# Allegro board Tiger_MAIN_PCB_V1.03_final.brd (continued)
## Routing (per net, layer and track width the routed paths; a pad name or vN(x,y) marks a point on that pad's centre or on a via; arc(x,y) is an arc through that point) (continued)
PMON_PSYS: length 6.6
  BOTTOM w0.203: R238.2 R218.2 231.98,84.12 R232.2 C720.1 232.37,85.95 233.77,85.95 234.94,87.12 U103.1
POWER_TP_ON: length 10.4
  TOP w0.076: 191.47,61.04 191.47,61.24 191.75,61.51 192.07,61.51 192.39,61.19 U1.AM11
  TOP w0.102: 191.47,61.04 191.47,61.04 191.32,60.88 189.93,60.88 189.76,60.7 189.76,59.93 189.4,59.57 188.77,59.57 188.61,59.72 186.1,59.72 184.97,58.59 R382.1
POWSW#: length 36.8
  TOP w0.305: 120.22,8.59 SW1.1 v2(120.22,12.58)
  LAY6 w0.102: v2(120.22,12.58) 121.23,11.58 132.77,11.58 134.59,13.39 v2(147.22,13.39)
  BOTTOM w0.102: D29.N 147.19,13.42 v2(147.22,13.39)
  BOTTOM w0.203: D29.N D17.N 145.2,13.35 R791.1
PROCHOT#_EC: length 6.1
  BOTTOM w0.114: U22.76 44.85,62.26 R426.2 44.23,61.94 42.73,61.94 R407.2 42.23,62.38 41.59,61.74 U23.2
PS_LATCH#: length 10.7
  BOTTOM w0.305: Q57.3 149.19,16.95 Q56.1 148.98,16.95 147.44,18.5 145.61,18.5 145.2,18.09 D17.P 144.49,16.99 143.96,17.52 R792.2
PS_S3CNTRL: length 298.5
  LAY3 w0.102: v2(166.39,35.76) 166.57,35.58 166.57,19.91 173.2,13.28 180.21,13.28 182.66,10.83 192.73,10.83 192.92,10.64 239.82,10.64 243.18,14 243.18,24.84 230.51,37.51 230.51,39.65 235.82,44.95 v2(235.82,46.06)
  LAY6 w0.102: v2(29.41,63.04) 32.24,63.04 42.82,52.46 74.63,52.46 75.53,51.56 89.59,51.56 89.82,51.79 91.92,51.79 93.85,49.86 109.56,49.86 110.37,50.68 111.68,50.68 115.41,46.95 122.79,46.95 124.66,45.08 130.08,45.08 130.83,45.83 135.73,45.83 148.23,33.33 163.96,33.33 v2(166.39,35.76)
  BOTTOM w0.102: v2(29.41,63.04) 29.41,62.15 28.51,61.25 Q45.1 ; Q21.1 v2(235.82,46.06)
  BOTTOM w0.305: Q45.1 27.28,61.25 26.92,61.61 R463.2 R809.2 26.09,64.35 Q46.3
PSMS: length 2
  BOTTOM w0.102: U95.20 73.27,99.52 72.32,100.47 R3009.1
PWM: length 4.9
  TOP w0.305: R3109.2 128.4,90.35 R3110.1 128.39,89.56 R528.1 128.24,88.64 U2529.16 126.28,89.78 R3106.1
PWR_LED: length 112.2
  TOP w0.102: Q49.1 101.93,14.42 v2(101.93,10.33)
  LAY3 w0.102: v2(45.29,64.02) 45.78,63.53 45.78,56.98 47.83,54.92 47.83,36.19 v2(44.43,32.79)
  LAY6 w0.102: v2(101.93,10.33) 101.8,10.2 98.92,10.2 96.35,12.77 92,12.77 89.43,10.2 70.8,10.2 67.13,13.86 57.86,13.86 54.77,16.95 54.77,21.21 53.07,22.92 51.54,22.92 44.43,30.03 v2(44.43,32.79)
  BOTTOM w0.102: v2(45.29,64.02) 45.54,64.02 45.7,63.86 U22.80
PWR_SW: length 20.2
  TOP w0.305: v2(76.25,101.73) 73.75,101.73 71.3,99.28 CN37.4
  BOTTOM w0.305: v2(76.25,101.73) C2781.1 76.25,100.85 75.27,99.87 U95.24
PWRONLATCHG: length 14.4
  TOP w0.305: v2(139.98,23.92) 139.98,16.93 v2(140.89,16.02)
  BOTTOM w0.305: C784.1 R788.1 143.14,15.99 R792.1 C785.2 v2(140.89,16.02) ; Q58.4 v2(139.98,23.92)
R_OUT+: length 1.6
  TOP w0.508: R630.2 7.13,11.5 CN14.2
R_OUT-: length 1.6
  TOP w0.508: CN14.1 R629.2
REXT: length 2
  BOTTOM w0.102: U2526.26 138.55,80.32 137.65,79.41 R2986.2
RLV_AMP: length 2.5
  BOTTOM w0.102: R2987.2 136.88,79.63 137.07,79.82 137.75,79.82 138.15,80.23 U2526.27
RLV_CFG: length 2.4
  BOTTOM w0.203: R2994.2 139.98,79.99 140.15,80.16 U2526.22
  BOTTOM w0.305: R2993.1 R2994.2
RLV_LNK: length 11.7
  TOP w0.152: U2525.7 136.87,73.25 v2(136.86,73.24)
  BOTTOM w0.152: v2(136.86,73.24) 138.31,73.24 140.9,75.83 140.9,76.56 R2996.1 140.44,79.88 140.55,79.99 U2526.21
ROP_SYS_PWROK: length 174.9
  TOP w0.076: 189.04,78.57 189.44,78.18 v2(189.44,78.01) 189.44,77.68 189.11,77.35 189.11,76.74 U1.B6
  TOP w0.109: 189.04,78.57 187.46,80.16 R15.2
  LAY3 w0.087: v2(59.52,57.73) 59.24,58.01 59.24,59.48 59.65,59.89 59.65,69.83 59.81,69.99 59.81,72.25 59.52,72.54 59.52,74.83 59.21,75.14 59.21,75.76 59.39,75.94 59.39,83.78 v2(60.13,84.51)
  LAY6 w0.087: v2(60.13,84.51) 60.14,84.5 84.09,84.5 95.24,73.35 111.09,73.35 111.78,74.04 121.11,74.04 124.34,70.81 138.59,70.81 139.73,71.95 149.85,71.95 152.13,74.23 164.7,74.23 165.47,75 v2(165.89,75)
  BOTTOM w0.102: 185.9,78.35 189.1,78.35 v2(189.44,78.01)
  BOTTOM w0.109: 185.9,78.35 181.82,78.35 180.03,80.15 175.65,80.15 173.88,78.38 168.9,78.38 166.24,75.71 166.24,75.34 v2(165.89,75) ; v2(59.52,57.73) U22.35
ROP_VCCST_PWRGD: length 4.3
  TOP w0.203: v2(47.53,66.66) 47.53,66.09 R830.1 47.21,65.77 R23.2 46.36,65.78 Q74.1
  BOTTOM w0.109: U22.87 47.53,66.66 v2(47.53,66.66)
RSET: length 5.1
  BOTTOM w0.102: U9.46 124.4,37.14 123.61,36.36 122.56,36.36 121.66,35.46 120.96,35.46 R307.2
RSTZ: length 3.3
  BOTTOM w0.254: U95.22 74.27,100.63 C2786.1 R802.2 R3008.2
RTA: length 1
  TOP w0.305: R958.2 120.28,83.06 U2529.8
RTC_RST*: length 30.1
  TOP w0.076: U1.AM16 v2(196.05,60.78)
  LAY3 w0.076: 195.99,57.01 196.42,57.43 196.42,60.41 v2(196.05,60.78)
  LAY3 w0.102: 195.99,57.01 194.65,55.66 193.81,55.66 193.08,54.94 189.98,54.94 186.54,51.49 182.49,51.49 177.77,46.77 v2(177.77,45.13)
  BOTTOM w0.152: R6.1 v2(177.77,45.13) 177.77,44.45 C3.1
RTC_X1: length 24.3
  TOP w0.076: U1.AM18 v2(196.96,60.78)
  LAY3 w0.089: v2(188.02,46.61) 189.11,47.7 190.34,47.7 190.56,47.91 190.56,49.07 192.31,50.82 192.58,50.82 198.24,56.49 198.24,59.69 197.14,60.78 v2(196.96,60.78)
  BOTTOM w0.076: R5.2 187.93,45.99 C6.1 187.93,44.74
  BOTTOM w0.102: R5.2 187.86,46.44 v2(188.02,46.61) ; X2.2 187.93,44.26 187.93,44.74
RTC_X2: length 23.5
  TOP w0.076: U1.AM20 v2(197.87,60.78)
  LAY3 w0.089: v2(197.87,60.78) 197.87,60.37 198.42,59.82 198.42,56.33 192.64,50.55 192.33,50.55 190.81,49.03 190.81,47.8 190.49,47.48 189.5,47.48 v2(188.63,46.61)
  BOTTOM w0.076: 188.75,44.74 C5.1 188.75,46 R5.1
  BOTTOM w0.102: X2.1 188.75,44.11 188.75,44.74 ; R5.1 188.81,46.44 v2(188.63,46.61)
S3_DISCHARGE: length 397.7
  TOP w0.203: v2(154.59,70.67) Q53.1 155.89,72.89 161.28,78.28 162.68,78.28 167.48,83.08 v2(167.48,85.39) ; v2(149.78,39.15) 147.08,41.85 Q67.1 ; Q66.1 178.01,88.05 v2(177.76,87.81)
  TOP w0.254: Q64.1 38.01,67.77 37.21,68.57 Q63.1
  TOP w0.305: v2(38.97,81.11) 38.97,72.72 38.55,72.3 38.07,72.3 Q63.1
  LAY3 w0.203: v2(167.47,36.79) 167.2,36.52 167.2,22.67 168.05,21.81 168.05,19.13 173.63,13.56 180.38,13.56 182.82,11.12 185.88,11.12 187.3,12.54 192.54,12.54 193.87,11.21 239.36,11.21 242.52,14.37 242.52,23.38 229.84,36.06 229.84,44.25 v2(230.7,45.11) ; v2(149.78,39.15) 152.77,42.15 152.77,46.31 148.87,50.21 148.87,57.21 152.39,60.73 152.39,68.47 v2(154.59,70.67)
  LAY3 w0.254: v2(167.48,85.39) 169.3,85.39 172.57,88.67 176.91,88.67 v2(177.76,87.81)
  LAY6 w0.203: v2(167.47,36.79) 166.17,36.79 163.43,34.04 154.88,34.04 v2(149.78,39.15) ; v2(154.59,70.67) 154.27,70.67 152.04,68.44 143.91,68.44 142.21,66.73 122.26,66.73 119.03,69.96 91.93,69.96 88.21,73.68 75.15,73.68 72.28,76.55 48.71,76.55 44.15,81.11 v2(41.36,81.11)
  BOTTOM w0.305: Q52.1 v2(230.7,45.11) ; v2(41.36,81.11) v2(38.97,81.11) 28.28,81.11 27.03,79.87 27.03,75.51 28.51,74.04 Q65.3 29.8,73.56 29.31,73.07 R814.1 R821.2
S4_DISCHARGE: length 5.8
  BOTTOM w0.102: R813.1 237.33,50.07 R812.2 238.65,50.07 239.65,49.07 Q62.3 240.76,49.07 241.14,49.45 Q61.1
SA0_DIM1: length 7.9
  TOP w0.102: CN1.256 173.61,14.89 173.35,15.16 172.4,15.16 170.25,13.01 R491.1 R489.1
SA1_DIM1: length 3.6
  TOP w0.102: R389.1 R436.1 171.98,12.09 172.61,12.72 CN1.260
SA_BOOT: length 1
  BOTTOM w0.305: U54.2 162.15,88.74 R258.1
SA_COPM: length 4.8
  BOTTOM w0.203: C312.1 244.03,91.54 R224.2 242,89.52 U103.24
SA_CSN: length 6.8
  BOTTOM w0.203: C806.2 243.25,84.24 R237.1 242.42,85.07 242.42,87.44 241.95,87.92 U103.28
SA_CSP: length 11.8
  BOTTOM w0.203: U103.27 242.17,88.32 242.8,87.68 242.8,85.21 243.07,84.94 244.77,84.94 244.98,84.74 244.98,84.12 R223.1 ; R223.1 244.73,82.8 R260.1 R221.1 ; R223.1 C311.1
SA_FCCM: length 98.6
  LAY3 w0.635: v1(158.82,88.74) 158.82,91.5 161.45,94.13 189.17,94.13 191.3,96.26 206.71,96.26 207.02,95.94 210.05,95.94 210.84,96.73 228.9,96.73 229.21,97.05 237.62,97.05 242.82,91.85 242.82,89.1 241.64,87.93 v1(241.64,87.18)
  BOTTOM w0.203: 241.5,87.32 241.3,87.52 U103.29
  BOTTOM w0.305: U54.7 v1(158.82,88.74)
  BOTTOM w0.635: 241.5,87.32 v1(241.64,87.18)
SA_HG_DRV: length 4
  TOP w0.635: v1(161.63,92.39) 161.61,92.37 R183.2
  BOTTOM w0.305: U54.1 161.45,89.69
  BOTTOM w0.635: v1(161.63,92.39) 161.45,92.22 161.45,89.69
SA_LG_DRV: length 4.8
  TOP w0.635: Q73.3 v1(162.42,87.07)
  BOTTOM w0.305: U54.5 159.55,87.36 159.85,87.07
  BOTTOM w0.635: 159.85,87.07 v1(162.42,87.07)
SA_PHASE: length 98.6
  LAY3 w0.254: v2(246.64,85.96) 246.11,86.5 244.35,86.5 243.58,85.72 240.01,85.72 238.95,86.78 237.93,86.78 236.28,88.44 236.28,89.11 233.99,91.4 233.54,91.4 232.31,92.62 210.96,92.62 210.41,93.17 206.24,93.17 205.84,92.78 204.67,92.78 203.99,93.46 201.47,93.46 200.79,92.78 192.41,92.78 191.29,91.66 168.01,91.66 v2(167.11,90.76)
  BOTTOM w0.203: v2(246.64,85.96) 247.15,85.45 247.15,83.08 246.4,82.33 245.8,82.33 R260.2
  BOTTOM w0.305: U54.8 159.55,89.55
  BOTTOM w0.508: C740.1 163.36,92.49 v1(163.35,92.49) 162.35,93.49 160.74,93.49 159.55,92.31 159.55,89.55
SA_PWM: length 91.3
  LAY3 w0.635: v1(163.48,87.1) 163.48,88.7 167.52,92.73 189.87,92.73 192.08,94.94 206.02,94.94 206.43,94.53 214.93,94.53 215.98,95.58 232.76,95.58 233.99,94.34 236.8,94.34 240.37,90.78 240.37,86.83 v1(240.72,86.48)
  BOTTOM w0.203: U103.30 240.52,86.66
  BOTTOM w0.305: U54.3 162.35,88.24 163.48,87.11 v1(163.48,87.1)
  BOTTOM w0.635: 240.52,86.66 240.7,86.48 v1(240.72,86.48)
SD_CDZ: length 20.2
  TOP w0.102: v2(73.76,99.95) 72.6,98.79 72.6,92.86 74.95,90.51 80.37,90.51 81.68,89.2 CN37.11
  BOTTOM w0.102: v2(73.76,99.95) 73.77,99.95 U95.21
SD_CLK: length 10.3
  TOP w0.102: v2(72.2,90.75) 73.8,89.15 CN37.5
  BOTTOM w0.102: v2(72.2,90.75) 71.14,91.81 71.14,96.2 71.35,96.41 U95.14
SD_CMD: length 12.3
  TOP w0.102: v2(67.23,93.79) 66.3,92.86 CN37.2
  BOTTOM w0.102: v2(67.23,93.79) 70.36,96.91 U95.15
SD_D0: length 13.2
  TOP w0.102: CN37.7 78.8,89.31 78.44,89.66 74.29,89.66 v2(73.12,90.83)
  BOTTOM w0.102: U95.13 72.02,91.93 v2(73.12,90.83)
SD_D1: length 13.2
  TOP w0.102: v2(74.02,90.77) 74.81,89.97 79.65,89.97 80.43,89.19 CN37.8
  BOTTOM w0.102: U95.12 72.77,92.02 v2(74.02,90.77)
SD_D2: length 15.5
  TOP w0.102: v2(65.94,93.77) 65.94,93.72 64.29,92.06 64.29,92.05 61.3,89.06 CN37.9
  BOTTOM w0.102: U95.17 70.09,97.91 v2(65.94,93.77)
SD_D3: length 13.9
  TOP w0.102: v2(66.58,93.79) 63.8,91.01 CN37.1
  BOTTOM w0.102: v2(66.58,93.79) 70.21,97.41 U95.16
SD_RCOMP: length 12.5
  TOP w0.254: v2(189.72,65.81) 189.72,66.08 U1.AB7
  TOP w0.305: v2(179.16,66.25) 179.33,66.08 R74.2
  LAY6 w0.254: v2(189.72,65.81) 189.72,65.65 189.32,65.26 186.37,65.26 185.87,65.76 179.65,65.76 v2(179.16,66.25)
SD_WP: length 14.4
  TOP w0.102: CN37.10 82.97,89.18 82.72,89.43 82.02,89.43 80.61,90.84 75.4,90.84 v2(74.58,91.66)
  BOTTOM w0.102: U95.10 73.77,92.47 v2(74.58,91.66)
SKL_CNL*: length 12.6
  TOP w0.076: R716.1 231.03,81.38 230.41,80.76 224.42,80.76 223.72,80.06 223.72,79.32 222.92,78.52 222.92,76.57 U1.C64
SLPS3#_CONTROL: length 28.2
  TOP w0.305: R807.2 v2(28.56,79.83)
  TOP w0.406: R810.2 29.95,61.58 v2(29.98,61.6)
  BOTTOM w0.305: R806.2 25.16,60.3 Q45.3 26.73,60.55 29.49,60.55 29.98,61.03 v2(29.98,61.6) 30.33,61.96 30.33,67 32.03,68.7 32.03,76.46 30.47,78.02 29.19,78.02 28.56,78.65 v2(28.56,79.83)
SM_INTRUDER*: length 27.2
  TOP w0.076: U1.AP16 v2(196.05,59.51)
  LAY3 w0.076: v2(196.05,59.51) 195.69,59.15 195.69,57.04
  LAY3 w0.102: 195.69,57.04 194.62,55.98 193.74,55.98 192.89,55.13 189.24,55.13 185.96,51.85 180,51.85 178.2,50.05 v2(175.49,50.05)
  BOTTOM w0.102: v2(175.49,50.05) 175.44,49.99 R12.1
SM_RCOMP_0: length 20
  TOP w0.254: U1.AR18 v2(196.96,58.88)
  TOP w0.305: R53.2 v2(182.94,49.12)
  LAY6 w0.152: 196.47,57.3 196.47,58.39 v2(196.96,58.88)
  LAY6 w0.254: 188.88,51.93 191.32,51.93 194.59,55.2 194.59,55.42 196.47,57.3
  LAY6 w0.305: 188.88,51.93 185.75,51.93 v2(182.94,49.12)
SM_RCOMP_1: length 16.6
  TOP w0.254: U1.AT18 v2(196.96,58.24)
  TOP w0.305: v2(189.51,48.1) 189.32,47.91 R52.2
  LAY3 w0.305: v2(189.51,48.1) 189.51,50.91 190.19,51.58 192.83,51.58 197.48,56.23 197.48,57.88 197.12,58.24 v2(196.96,58.24)
SM_RCOMP_2: length 18.2
  TOP w0.254: U1.AU18 v2(196.96,57.61)
  TOP w0.305: R51.2 v2(183.72,49.12)
  LAY3 w0.152: v2(196.96,57.61) 196.96,57.17 196.77,56.99
  LAY3 w0.254: 184,49.41 185.21,50.62 188.38,50.62 191.15,53.39 192.73,53.39 194.29,54.95 194.73,54.95 196.77,56.99
  LAY3 w0.305: 184,49.41 184,49.4 v2(183.72,49.12)
SM_VREF_DQ1: length 88.7
  TOP w0.203: R512.2 v2(229.63,48.62)
  LAY3 w0.203: v2(229.63,48.62) 229.63,45.77 229.11,45.25 229.11,35.75 241.85,23.01 241.85,14.56 239.99,12.7 195.72,12.7 v2(195.03,12.01)
  BOTTOM w0.203: R476.1 v2(195.03,12.01)
SMB_CLK: length 17.8
  TOP w0.076: U1.R7 v2(189.63,69.01)
  TOP w0.109: Q2.3 175.88,72.97 176.12,72.73 177.96,72.73 178.63,72.06 178.63,71.27 R82.2 179.18,70.12 v2(179.11,70.04)
  LAY6 w0.076: v2(189.63,69.01) 189.27,69.38 188.27,69.38 188,69.64
  LAY6 w0.102: 188,69.64 179.51,69.64 v2(179.11,70.04)
SMB_CLK_BT: length 2.2
  BOTTOM w0.109: U22.110 53.12,72.55 52.78,72.89 52.78,72.89 R388.2
SMB_CLK_S2: length 103
  TOP w0.109: v2(136.05,28.85) 149.15,28.85 150.51,27.49 162.3,27.49 166.18,23.6 166.18,21.32 166.71,20.8 168.72,20.8 v2(169,21.08) 170.67,19.41 173.87,19.41 174.36,19.91 CN1.253 ; v2(171.21,70.25) 171.49,70.52 R85.1 171.51,72.02 Q2.2
  LAY3 w0.087: v2(171.21,70.25) 171.16,70.3 171.01,70.3 169.25,68.54 169.25,65.49 168.67,64.91 168.67,62.44 167.41,61.17 167.41,58.78 168.74,57.45 168.74,56.23 169.31,55.66 169.31,53.48 169.98,52.8 169.98,52.41 169.64,52.07 169.64,48.05 169.95,47.74 169.95,39.48 169.38,38.91 169.38,24.55 169.66,24.27 169.66,21.74 v2(169,21.08)
  BOTTOM w0.109: R3001.2 135.95,28.95 v2(136.05,28.85)
SMB_DATA: length 21.1
  TOP w0.076: U1.R8 v2(190.27,69.01)
  TOP w0.109: Q3.3 175.29,69.63 175.79,70.13 175.79,71.65 176.31,72.17 177.89,72.17 178.22,71.84 178.22,70.27 v2(178.45,70.04) 178.64,69.86 R83.2
  LAY6 w0.076: v2(190.27,69.01) 189.74,69.55 188.48,69.55 188.35,69.67
  LAY6 w0.102: 188.35,69.67 188.12,69.91 182.12,69.91 181.56,70.47 178.88,70.47 v2(178.45,70.04)
SMB_DATA_BT: length 2
  BOTTOM w0.109: R393.2 53.52,73.72 U22.111
SMB_DATA_S2: length 104.6
  TOP w0.109: v2(170.98,68.65) 171,68.67 R84.1 171.62,68.68 Q3.2 ; v2(136.11,28.28) 149.03,28.28 150.36,26.95 162.15,26.95 165.69,23.4 165.69,21.1 166.5,20.29 v2(169.09,20.29) 170.46,18.92 173.67,18.92 174.11,18.47 CN1.254
  LAY3 w0.087: v2(169.09,20.29) 170.2,21.4 170.2,24.48 169.88,24.8 169.88,38.71 170.44,39.27 170.44,47.9 170.11,48.24 170.11,51.82 170.46,52.18 170.46,53.02 169.78,53.7 169.78,55.96 169.23,56.51 169.23,57.79 167.87,59.15 167.87,60.96 169.16,62.24 169.16,64.66 169.74,65.25 169.74,68.32 170.85,69.43 171.07,69.43 171.32,69.18 171.32,69 v2(170.98,68.65)
  BOTTOM w0.109: R3000.2 135.98,28.15 v2(136.11,28.28)
SMB_L1CLK_PCH: length 143.5
  TOP w0.076: R57.2 179.02,68.26 v2(179.08,68.33) ; U1.W3 187.48,67.45 187.29,67.57 187.1,67.57 186.86,67.52 186.6,67.57 185.09,67.57 185.01,67.49 182.92,67.49
  TOP w0.102: R57.2 179.52,67.19 182.35,67.19 182.65,67.49 182.92,67.49
  LAY6 w0.076: 176.55,67.64 177.61,68.7 178.71,68.7 v2(179.08,68.33)
  LAY6 w0.102: 176.55,67.64 174.54,67.64 173.94,68.23 164.55,68.23 163.56,69.22 155.8,69.22 153.31,66.73 144.81,66.73 141.76,63.69 122.37,63.69 117.38,68.68 91.59,68.68 87.71,72.55 73.31,72.55 71.56,74.3 55.31,74.3 v2(54.36,75.25)
  BOTTOM w0.114: R396.1 v2(54.36,75.25)
SMB_L1DATA_PCH: length 140.3
  TOP w0.076: v2(181.73,68.32) 181.78,68.26 R58.2 181.82,67.75 186.56,67.75 186.82,67.69 186.9,67.69 187.08,67.73 187.34,67.73 187.42,67.68 187.71,67.68 U1.V3
  LAY6 w0.076: v2(181.73,68.32) 181.34,67.93 180.17,67.93 179.19,68.91 176.62,68.91 176.45,68.73 176.13,68.73
  LAY6 w0.102: 176.13,68.73 172.2,68.73 171.42,69.52 155.69,69.52 153.12,66.94 144.72,66.94 141.93,64.14 122.62,64.14 117.82,68.94 91.88,68.94 87.88,72.94 73.7,72.94 72.07,74.58 57.76,74.58 v2(57.04,75.3)
  BOTTOM w0.114: R397.1 v2(57.04,75.3)
SMBCLK: length 5.3
  BOTTOM w0.109: R326.2 121.22,46.26 121.53,45.94 123.4,45.94 124,45.34 U9.14
SMBDATA: length 5
  BOTTOM w0.109: U9.15 124.4,45.65 R323.1 R321.1 122,46.47 R325.2
SMC_EXTSMI#: length 136.5
  TOP w0.076: U1.L6 v2(188.98,71.02) ; R61.2 179.78,72.2 v2(180.16,71.82)
  LAY3 w0.102: v2(188.98,71.02) 188.86,70.9 181.16,70.9 180.24,71.82 v2(180.16,71.82) ; v2(71.34,61.98) 73,63.65 73,72.2 v2(74.45,73.64)
  LAY6 w0.076: v2(180.16,71.82) 179.77,71.43 177.89,71.43 177.58,71.12 176.37,71.12
  LAY6 w0.102: v2(74.45,73.64) 74.67,73.43 88.03,73.43 91.88,69.58 118.6,69.58 121.72,66.45 142.33,66.45 144.04,68.16 152.62,68.16 155.28,70.81 165.85,70.81 166.72,71.67 171.87,71.67 173.61,69.93 174.85,69.93 176.03,71.12 176.37,71.12
  BOTTOM w0.102: R403.1 v2(71.34,61.98)
SMC_ONOFF#: length 131.4
  LAY3 w0.102: v2(59.21,50.59) 59.2,50.61 59.2,56.69 58.79,57.09 58.79,59.53 59.38,60.12 59.38,70.44 v2(59.33,70.49)
  LAY6 w0.102: v2(147.19,17.95) 136.95,28.19 136.95,35.09 134.8,37.24 133.68,37.24 127.56,43.35 119.87,43.35 119.44,43.79 116.44,43.79 113.96,46.26 110.57,46.26 108.53,48.31 96.98,48.31 93.58,44.9 87.28,44.9 86.26,45.92 67.05,45.92 61.88,51.09 59.71,51.09 v2(59.21,50.59)
  BOTTOM w0.102: v2(59.33,70.49) 59.12,70.7 U22.125
  BOTTOM w0.203: v2(147.19,17.95) 147.19,17.95 D29.P
SMC_RUNTIME_SCI#: length 151
  TOP w0.076: v2(190.9,70.08) 191.16,70.47 U1.N9 ; R62.2 180.56,72.07 v2(180.81,71.82)
  LAY3 w0.102: v2(65.31,75.59) 65.33,75.56 v2(65.33,61.26) ; v2(180.81,71.82) 180.89,71.82 181.38,71.33 188.42,71.33 188.56,71.47 189.21,71.47 190.12,70.56 190.43,70.56 v2(190.9,70.08)
  LAY6 w0.076: v2(180.81,71.82) 180.81,71.63 180.42,71.24 178.08,71.24 177.56,70.72
  LAY6 w0.102: 177.56,70.72 176.09,70.72 175.07,69.71 173.49,69.71 171.8,71.4 166.93,71.4 166.06,70.52 155.28,70.52 152.67,67.92 144.12,67.92 142.44,66.23 121.29,66.23 118.31,69.21 91.95,69.21 87.97,73.2 74.3,73.2 71.91,75.59 v2(65.31,75.59)
  BOTTOM w0.102: R410.1 65.33,61.25 v2(65.33,61.26)
SMC_SHUTDOWN#: length 147.8
  LAY3 w0.102: v2(43.35,64.87) 43.99,64.24 43.99,55.98 44.93,55.04 44.93,53.79 v2(47.25,51.47)
  LAY6 w0.102: v2(155.07,17.72) 150.32,22.47 150.32,26.02 134.33,42.01 131.16,42.01 129.46,43.71 120.43,43.71 119.22,44.92 115.73,44.92 114.04,46.6 110.81,46.6 108.84,48.57 96.88,48.57 93.52,45.21 87.6,45.21 86.58,46.22 67.25,46.22 62.01,51.47 v2(47.25,51.47)
  BOTTOM w0.102: v2(43.35,64.87) 44.04,64.87 R395.2
  BOTTOM w0.305: Q57.1 151.2,15.42 R789.2 153.66,15.42 155.07,16.82 v2(155.07,17.72)
SMC_WAKE_SCI#: length 142.1
  TOP w0.076: U1.AM15 v2(195.13,60.78)
  LAY3 w0.076: v2(195.13,60.78) 194.67,60.32 194.67,59.81 194.21,59.36 194.04,59.36 193.67,58.99 193.67,57.97 192.19,56.49 190.59,56.49 190.11,56.97 188.37,56.97 187.62,56.22 182.82,56.22 179.74,53.13 176.13,53.13
  LAY3 w0.102: 176.13,53.13 175.62,53.13 173.3,50.81 v2(173.3,49.21)
  LAY6 w0.102: v2(72.17,57.46) 72.79,58.09 91.95,58.09 92.86,57.18 97.66,57.18 98.51,56.33 113.51,56.33 118.46,51.38 143.06,51.38 146.32,48.12 155.26,48.12 156.65,49.5 163.37,49.5 164.12,48.74 167.91,48.74 168.95,49.79 172.71,49.79 v2(173.3,49.21)
  BOTTOM w0.102: R412.1 71.47,61.14 72.2,60.41 72.2,57.5 v2(72.17,57.46) ; R19.2 172.88,49.63 v2(173.3,49.21)
SOC_CATERR*: length 11.9
  TOP w0.076: R29.2 227.2,83.51 226.57,82.87 TP18.1 226.3,82.25 224.35,82.25 222.83,80.73 222.83,79.66 221.99,78.82 221.99,77.83 221.83,77.68 221.83,77.32 221.87,77.22 221.87,77.03 221.83,76.94 221.83,76.69 221.97,76.21 221.97,76.09 222.05,75.83 222.05,75.83 U1.D63
SOC_THRMTRIP*: length 12
  TOP w0.076: U1.C63 222.08,76.46 222,76.71 222,76.89 222.06,77.08 222.06,77.23 222,77.34 222,77.6 222.22,77.82 222.22,78.82 223.01,79.6 223.01,80.68 224.41,82.08 227.09,82.08 227.47,82.46 TP20.1 227.97,83.48 R28.2
SPK_L+: length 269.7
  TOP w0.508: v1(245.86,18.65) 245.84,18.67 R628.1
  LAY6 w0.508: v1(13.58,24.27) 13.58,25.52 22.15,34.1 38.02,34.1 46.06,26.05 46.06,14.23 47.7,12.59 57.45,12.59 60.8,9.24 89.83,9.24 92.09,11.5 95.52,11.5 97.75,9.27 117.21,9.27 118.51,10.57 125.92,10.57 127.16,9.33 145.1,9.33 147.41,11.64 150.75,11.64 153.13,9.26 237.53,9.26 243.53,15.26 243.53,18.86 244.23,19.55 244.95,19.55 v1(245.86,18.65)
  BOTTOM w0.203: 13.84,23.37 14.33,22.87 U16.42
  BOTTOM w0.406: v1(13.58,24.27) 13.84,24.02 13.84,23.37
SPK_L-: length 266.5
  TOP w0.508: v1(244.64,18.77) 244.57,18.83 R627.1
  LAY6 w0.508: v1(14.45,24.39) 14.45,25.47 22.4,33.42 37.65,33.42 45.43,25.64 45.43,13.89 47.39,11.92 57,11.92 60.31,8.61 90.12,8.61 92.37,10.85 95.25,10.85 97.46,8.63 117.68,8.63 119,9.95 125.64,9.95 126.9,8.7 145.43,8.7 147.75,11.01 150.44,11.01 152.82,8.63 237.97,8.63 244.64,15.3 v1(244.64,18.77)
  BOTTOM w0.203: U16.43 14.73,22.76
  BOTTOM w0.305: 14.73,22.76 14.73,23.19
  BOTTOM w0.406: v1(14.45,24.39) 14.53,24.3 14.53,23.38 14.73,23.19
SPK_R+: length 19.3
  TOP w0.508: v2(15.99,23.05) 15.99,22.92 17.54,21.37 17.54,16.92 12.15,11.53 R630.1
  BOTTOM w0.203: v2(15.99,23.05) 15.53,22.59 U16.45
SPK_R-: length 18.1
  TOP w0.508: R629.1 12.46,12.75 16.87,17.16 16.87,21.1 15.39,22.58 v2(15.39,23.18)
  BOTTOM w0.203: v2(15.39,23.18) 15.13,22.93 U16.44
SRTCRST*: length 28.9
  TOP w0.076: v2(196.96,60.15) 196.57,60.54 U1.AN18
  LAY3 w0.076: 194.77,55.41 196.6,57.24 196.6,59.79 v2(196.96,60.15)
  LAY3 w0.102: v2(179.18,45.13) 179.18,47.78 182.59,51.19 186.71,51.19 190.26,54.75 193.24,54.75 193.9,55.41 194.77,55.41
  BOTTOM w0.152: R7.1 v2(179.18,45.13) 179.18,44.44 C4.1
SSD_CK_REQ_N: length 17.9
  TOP w0.102: R181.1 82.85,50.62 81.84,49.61 81.84,41.84 80.42,40.42 CN5.52
SSD_CLK_REQ*: length 123.5
  TOP w0.076: R253.2 183.73,52.69 184.76,53.73 186.82,53.73 187.47,54.38 187.8,54.38 187.99,54.57 187.99,55.11 188.14,55.27 188.14,55.65 188.27,55.77 188.27,56.37 188.61,56.71 188.98,56.71 189.4,57.13 189.4,57.53 189.69,57.82 189.69,58.18 U1.AT7
  TOP w0.102: v2(81.87,57.3) 81.9,57.26 R181.2 81.9,56.19 R180.2 ; v2(180.52,50.19) 181.11,49.6 183.1,49.6 183.32,49.82 183.32,51.15 R253.2
  LAY6 w0.102: v2(180.52,50.19) 180.43,50.19 179.48,49.23 173.94,49.23 173.41,48.7 171.11,48.7 170.52,49.3 168.95,49.3 168.05,48.4 165.04,48.4 164.55,47.9 163.52,47.9 162.5,48.92 156.86,48.92 155.55,47.61 145.97,47.61 142.64,50.94 118.17,50.94 113.32,55.78 97.81,55.78 96.87,56.73 92.56,56.73 91.81,57.48 82.05,57.48 v2(81.87,57.3)
SSD_PCIE_CLK_DN: length 180.9
  TOP w0.076: U1.B42 211,77.01 211.32,77.33 211.32,81 211.05,81.27 v2(210.35,81.27)
  TOP w0.109: R187.1 90.29,39.76 90.73,39.76 91.22,39.76 v2(91.42,39.96)
  LAY3 w0.087: v2(98.97,77.75) 99.8,77.75 100.49,77.06 100.49,73.16 87.06,59.73 87.06,55.3 83.55,51.79 83.55,43.67 87.47,39.75 91.2,39.75 v2(91.42,39.96)
  LAY6 w0.076: 189.9,81.01 189.92,81.01 190.79,81.89 197.21,81.89 198.86,83.54 199.81,83.54 201.59,85.31 202.77,85.31 205.8,82.29 207.68,82.29 208.7,81.27 v2(210.35,81.27)
  LAY6 w0.087: v2(98.97,77.75) 102.47,77.75 104.41,79.69 114.61,79.69 117.56,76.73 123.81,76.73 125.54,78.47 130.35,78.47 130.66,78.16 135.79,78.16 137.36,76.59 139.74,76.59 140.85,77.69 148.41,77.69 149.95,79.23 155.2,79.23 157.73,81.76 171.94,81.76 172.78,80.93 173.74,80.93 174.69,81.87 177.13,81.87 177.68,82.42 185.13,82.42 186.54,81.01 189.9,81.01
SSD_PCIE_CLK_DP: length 181
  TOP w0.076: U1.A42 211.16,77.61 211.16,80.93 210.98,81.11 210.77,81.11 210.67,81.01 210.67,80.75 210.59,80.67 v2(210.35,80.67)
  TOP w0.109: R194.1 90.27,39.54 90.73,39.54 91.24,39.54 v2(91.42,39.36)
  LAY3 w0.087: v2(98.97,77.15) 99.39,77.57 99.72,77.57 100.3,76.98 100.3,73.23 86.88,59.81 86.88,55.38 83.36,51.86 83.36,43.6 87.39,39.56 91.21,39.56 v2(91.42,39.36)
  LAY6 w0.076: 189.9,80.83 189.97,80.83 190.86,81.72 197.28,81.72 198.93,83.37 199.88,83.37 201.66,85.15 202.7,85.15 205.73,82.13 207.61,82.13 208.63,81.11 209.98,81.11 210.05,81.03 210.05,80.78 210.16,80.67 v2(210.35,80.67)
  LAY6 w0.087: 189.9,80.83 186.46,80.83 185.05,82.24 177.76,82.24 177.21,81.69 174.76,81.69 173.82,80.74 172.7,80.74 171.86,81.58 157.81,81.58 155.28,79.05 150.03,79.05 148.49,77.51 140.92,77.51 139.82,76.41 137.28,76.41 135.71,77.97 130.59,77.97 130.27,78.29 125.62,78.29 123.88,76.55 117.49,76.55 114.53,79.51 104.48,79.51 102.55,77.57 99.32,77.57 99.18,77.43 99.18,77.36 v2(98.97,77.15)
SSD_PEDET: length 126.6
  TOP w0.076: U1.G4 188.48,73.9 188.22,73.64 186.24,73.64 v2(185.54,72.94)
  TOP w0.102: R174.2 90.78,35.13 98.61,42.96 102.72,42.96 104.92,45.16 104.92,58.57 v2(107.49,61.13)
  LAY6 w0.076: 177.02,71.76 177.35,72.09 178.88,72.09 179.24,72.45 183.29,72.45 184.14,73.3 185.16,73.3 185.51,72.94 v2(185.54,72.94)
  LAY6 w0.102: 177.02,71.76 172.94,71.76 172.28,72.42 153,72.42 150.67,70.09 141.51,70.09 140.3,68.88 122.66,68.88 120.01,71.53 115.93,71.53 v2(115.85,71.46)
  BOTTOM w0.102: v2(107.49,61.13) 115.85,69.5 v2(115.85,71.46)
SSD_SATA_DEVSLP: length 136.6
  TOP w0.076: v2(179.53,71.81) 179.91,71.43 181.83,71.43 182.95,72.55 186.46,72.55 U1.J1
  TOP w0.102: R175.1 v2(76.77,57.11)
  LAY3 w0.102: v2(76.81,76.37) 76.77,76.33 v2(76.77,57.11)
  LAY6 w0.076: v2(179.53,71.81) 179.53,71.78 179.42,71.66 177.79,71.66 177.48,71.34 176.6,71.34
  LAY6 w0.102: 176.6,71.34 172.64,71.34 171.96,72.02 153.8,72.02 151.34,69.55 142.65,69.55 140.85,67.75 123.16,67.75 119.88,71.03 94.15,71.03 88.27,76.91 77.35,76.91 v2(76.81,76.37)
SSD_SATA_RXN1: length 104.2
  TOP w0.076: v2(197.92,73.74) 198.02,73.74 U1.G21
  TOP w0.109: C2840.1 106.5,72.47 106.78,72.19 110.05,72.19 112.58,74.72 112.58,76.49 v2(112.39,76.68)
  LAY6 w0.076: 188.39,77.48 188.4,77.47 188.4,77.47 188.44,77.43 188.58,77.43 188.59,77.44 196.37,77.44 197.33,76.49 197.33,74.15 197.49,73.99 197.78,73.99 197.92,73.85 v2(197.92,73.74)
  LAY6 w0.087: v2(112.39,76.68) 112.59,76.48 112.59,76.13 113.44,75.28 123.49,75.28 124.09,74.67 134.16,74.67 134.47,74.36 145.24,74.36 145.88,75 149.45,75 151.16,76.72 159.07,76.72 160.93,78.57 164.41,78.57 165.31,79.47 166.81,79.47 167.65,78.63 171.91,78.63 172.59,77.96 175.08,77.96 176.78,79.65 180.28,79.65 181.4,78.53 187.33,78.53 188.16,77.7 188.17,77.7 188.39,77.48
SSD_SATA_RXP1: length 104.2
  TOP w0.076: U1.F21 198.02,74.39 v2(197.92,74.39)
  TOP w0.109: v2(112.99,76.68) 112.8,76.49 112.8,74.63 110.14,71.97 106.78,71.97 106.5,71.7 C2841.1
  LAY6 w0.076: v2(197.92,74.39) 197.68,74.15 197.56,74.15 197.49,74.22 197.49,76.56 196.44,77.61 188.51,77.61
  LAY6 w0.087: v2(112.99,76.68) 112.77,76.46 112.77,76.21 113.52,75.46 123.56,75.46 124.17,74.85 134.23,74.85 134.54,74.54 145.16,74.54 145.8,75.19 149.37,75.19 151.08,76.9 159,76.9 160.85,78.75 164.33,78.75 165.23,79.66 166.89,79.66 167.73,78.82 171.98,78.82 172.66,78.14 175.01,78.14 176.7,79.83 180.36,79.83 181.48,78.72 187.4,78.72 188.51,77.61
SSD_SATA_TXN1: length 114.4
  TOP w0.076: U1.D21 198.61,75.76 198.89,76.04 198.89,76.25 199.03,76.59 199.03,76.67 199.03,76.72 199.03,77.75 197.57,79.21 197.57,81.79 199.03,83.25 v2(199.03,85.38)
  TOP w0.109: C2843.1 104.8,79.75 104.51,80.04 104.51,80.2 105.04,80.73 106.68,80.73 v2(106.86,80.55)
  LAY6 w0.076: 189.9,82.15 190.03,82.15 190.04,82.15 196.84,82.15 198.94,84.26 198.94,85.29 v2(199.03,85.38)
  LAY6 w0.087: v2(106.86,80.55) 107.01,80.7 114.55,80.7 118.01,77.24 123.59,77.24 125.28,78.94 130.62,78.94 130.87,78.7 136.28,78.7 136.7,78.28 145.45,78.28 146.3,79.14 149,79.14 149.7,79.84 154.18,79.84 156.61,82.26 165.18,82.26 165.26,82.34 175.94,82.34 177.37,83.77 185.25,83.77 186.58,82.44 186.78,82.44 187.08,82.15 189.9,82.15
SSD_SATA_TXP1: length 114.7
  TOP w0.076: U1.C21 198.61,76.33 198.82,76.53 198.85,76.63 198.87,76.74 198.87,77.68 197.4,79.15 197.4,81.86 198.86,83.32 198.86,84.87 198.76,84.97 198.28,84.97 198.19,85.06 198.19,85.22 198.35,85.38 v2(198.43,85.38)
  TOP w0.109: v2(106.86,81.15) 106.65,80.95 104.95,80.95 104.29,80.29 104.29,80.04 104.01,79.75 C2842.1
  LAY6 w0.076: 189.9,82.33 189.91,82.33 189.92,82.32 196.77,82.32 198.77,84.32 198.77,84.94 198.68,85.03 198.51,85.03 198.43,85.11 v2(198.43,85.38)
  LAY6 w0.087: 189.9,82.33 187.15,82.33 186.86,82.62 186.66,82.62 185.32,83.96 177.3,83.96 175.87,82.52 165.18,82.52 165.1,82.44 156.53,82.44 154.11,80.02 149.62,80.02 148.93,79.32 146.23,79.32 145.37,78.46 136.78,78.46 136.36,78.88 130.94,78.88 130.7,79.12 125.21,79.12 123.51,77.43 118.09,77.43 114.63,80.89 107.12,80.89 v2(106.86,81.15)
SSTCMP: length 2.6
  TOP w0.203: R3093.1 128.59,88.17 127.26,88.17 127.08,87.99 U2529.15
STATUS: length 2.8
  TOP w0.203: R3112.1 128.7,87.19 128.22,87.66 127.39,87.66 127.07,87.35 U2529.14
SUS_CK: length 168.5
  TOP w0.076: v2(191.84,47.87) 192.47,48.51 192.47,49.27 193.13,49.93 193.13,50.69 196,53.56 196,55.16 196.27,55.43 U1.BA17
  TOP w0.102: v2(80.46,36.32) 80.37,36.42 CN5.68
  LAY3 w0.076: v2(191.84,47.87) 191.84,46.39 183.79,38.34 177.34,38.34 177.01,38.01 176.32,38.01
  LAY3 w0.102: v2(173.26,38.01) 176.32,38.01
  LAY6 w0.102: v2(80.46,36.32) 84.01,39.87 87.01,39.87 91.03,43.89 93.57,43.89 97.4,47.72 107.38,47.72 109.54,45.56 112.51,45.56 114.79,43.29 118.81,43.29 119.28,42.82 127.35,42.82 135.34,34.83 135.34,31.4 132.69,28.76 132.69,25.79 v2(133.05,25.43) 140.02,18.46 141.62,18.46 143.01,17.08 158.07,17.08 160.9,19.91 160.9,28.33 170.58,38.01 v2(173.26,38.01)
  BOTTOM w0.102: R8.2 191.85,47.86 v2(191.84,47.87) ; R3004.2 v2(133.05,25.43)
SW1: length 8.7
  BOTTOM w0.203: U71.18 18.07,71.34
  BOTTOM w0.635: 18.78,71.34 C767.2 ; 18.78,71.34 19.53,71.34 22.62,74.43 v1(22.62,76.55) ; 18.78,71.34 18.07,71.34
SW2: length 7.2
  BOTTOM w0.203: U71.8 13.86,71.34
  BOTTOM w0.635: v1(10.7,75.57) 10.7,72.82 12.18,71.33 C780.1 12.92,71.34 13.86,71.34
SYNC: length 19.2
  TOP w0.076: U1.BA22 198.2,54.99 198.2,54.21 197.45,53.46 197.45,51.91 195.19,49.65 195.19,47.49 194.19,46.49 192.06,46.49 190.21,44.64
  TOP w0.102: R799.2 189.77,44.2 190.21,44.64
  TOP w0.109: R620.2 188.96,42.01 R799.2
TBCLK: length 1.8
  BOTTOM w0.109: R399.2 45.3,65.78 45.37,65.86 U22.85
TBDATA: length 1.9
  BOTTOM w0.109: U22.86 45.64,66.26 45.34,66.56 R404.2
TEMP_ALERT#: length 240
  TOP w0.102: v2(243.81,79.39) U5.6 243.81,77.27 244.42,76.66 R523.2
  LAY3 w0.102: v2(48.81,75.41) 48.81,87.87 50.88,89.94 v2(50.88,93.43)
  LAY6 w0.102: v2(50.88,93.43) 51.44,93.99 53.42,93.99 54.03,93.38 58.64,93.38 58.9,93.63 60.22,93.63 60.47,93.38 83.83,93.38 86.54,90.66 112.15,90.66 114.58,93.1 127.69,93.1 131.84,88.95 134.74,88.95 135.97,87.71 141.89,87.71 150.77,96.59 170.02,96.59 172.39,94.22 181.03,94.22 181.97,93.28 189.56,93.28 192.1,95.82 200.48,95.82 206.24,90.05 207.26,90.05 209.59,87.71 216.38,87.71 216.74,87.35 220.02,87.35 221.63,88.96 222.46,88.96 225.19,86.23 232.71,86.23 233.28,86.8 236.23,86.8 237.3,85.72 238.26,85.72 239.41,84.57 241.16,84.57 241.66,84.07 241.66,79.45 242.4,78.71 243.63,78.71 243.81,78.89 v2(243.81,79.39)
  BOTTOM w0.102: R458.2 v2(48.81,75.41)
TLS_CONFIDENTIALITY: length 19.6
  TOP w0.076: v2(181.46,71.82) 181.35,71.94 R90.1 181.35,72.5 R91.2 ; U1.R10 v2(191.54,69.01)
  LAY3 w0.102: v2(181.46,71.82) 181.46,71.98 181.96,72.47 188.61,72.47 189.27,71.81 193.36,71.81 193.86,71.32 193.86,69.63 193.67,69.44 191.96,69.44 v2(191.54,69.01)
TXN0_LVDS: length 2.5
  BOTTOM w0.109: C281.2 145.56,85.87 145.35,85.87 144.8,85.31 144.41,85.31 144.31,85.21 U2526.5
TXN1_LVDS: length 2.5
  BOTTOM w0.109: C2846.2 145.56,83.34 145.25,83.34 144.5,84.1 144.25,84.1 144.17,84.01 U2526.8
TXP0_LVDS: length 2.5
  BOTTOM w0.109: U2526.4 144.31,85.61 144.39,85.53 144.7,85.53 145.26,86.09 145.57,86.09 C2850.2
TXP1_LVDS: length 2.5
  BOTTOM w0.109: C2847.1 145.57,83.56 145.34,83.56 144.59,84.31 144.31,84.31 144.21,84.41 U2526.7
USB2_COMP: length 11.7
  TOP w0.254: v2(179.79,66.26) 179.92,66.13 179.92,65.24 R66.2 ; v2(189.16,65.81) 189.26,65.91 U1.AB6
  LAY6 w0.254: v2(189.16,65.81) 189.07,65.73 186.89,65.73 186.44,66.18 179.88,66.18 v2(179.79,66.26)
USB2_DN*<1>: length 206.1
  TOP w0.076: U1.AB9 v2(190.9,65.81)
  TOP w0.109: v2(9.36,87.32) 9.01,87.66 9.01,88.29 FIL5.1
  LAY6 w0.076: 176.13,66.85 176.15,66.85 176.16,66.86 182.11,66.86 182.28,67.03 186.35,67.03 187.08,66.29 190.99,66.29 191.14,66.14 191.14,66.05 v2(190.9,65.81)
  LAY6 w0.087: 176.13,66.85 173.08,66.85 172.6,67.34 171.92,67.34 171.21,66.63 170.24,66.63 169.37,67.5 163.34,67.5 162.96,67.88 155.66,67.88 149.67,61.9 122.64,61.9 116.9,67.64 91.64,67.64 87.45,71.83 72.92,71.83 71.19,73.56 46.91,73.56 39.95,80.51 39.95,85.9 37.29,88.57 34.37,88.57 33.72,87.93 29.63,87.93 27.78,89.78 22.36,89.78 20.78,88.2 9.06,88.2 8.77,87.92 8.77,87.7 8.85,87.62 9.25,87.62 9.36,87.52 v2(9.36,87.32)
USB2_DN*<2>: length 174.1
  TOP w0.076: U1.AD6 v2(188.98,64.75)
  TOP w0.109: FIL15.1 36.36,88.15 v2(36.27,88.06)
  LAY6 w0.087: v2(188.98,64.75) 189.07,64.75 189.46,64.36 189.46,64.21 189.3,64.05 188.79,64.05 188.26,64.59 184.02,64.59 183.5,65.11 179.67,65.11 178.91,65.87 176.49,65.87 176.25,66.11 176.13,66.11 176.13,66.12 169.75,66.12 169.02,66.85 155.62,66.85 149.97,61.2 122.16,61.2 116.36,67.01 91.42,67.01 87.13,71.29 69.96,71.29 68.42,72.83 45.84,72.83 35.71,82.96 35.71,87.75 36.03,88.06 v2(36.27,88.06)
USB2_DN*<3>: length 102.3
  TOP w0.076: U1.AH3 188.15,61.87 187.99,61.7 187.6,61.7 187.55,61.65 187.42,61.61 187.22,61.56 187.09,61.56 186.96,61.61 186.95,61.61 186.75,61.61 186.63,61.55 186.62,61.55 186.11,61.55 185.86,61.8 183.2,61.8 182.44,61.04 177.7,61.04 176.4,59.75 176.4,59.72 176.39,59.71
  TOP w0.102: 176.13,59.45 176.39,59.71
  TOP w0.109: CN26.5 125.15,14.36 125.29,14.22 126.51,14.22 v2(126.69,14.4) ; v2(171.28,37.11) 171.1,37.28 171.1,50.74 174.83,54.48 174.83,58.15 176.13,59.45
  LAY6 w0.087: v2(171.28,37.11) 171.08,36.91 171.08,30.02 161.95,20.89 161.95,19.75 157.43,15.24 126.34,15.24 125.88,14.77 125.88,14.13 126,14 126.29,14 126.4,14.12 126.4,14.29 126.51,14.4 v2(126.69,14.4)
USB2_DN*<4>: length 187.4
  TOP w0.076: U1.AD9 191.21,65.05 v2(190.9,64.75)
  TOP w0.109: FIL9.3 45.69,20.41 45.23,20.41 44.95,20.7 44.95,22.98 60.42,38.45 91.25,38.45 95.82,43.03 95.82,59.1 96.84,60.12 96.84,64.31 98.21,65.68 v2(99.19,65.68)
  LAY6 w0.087: v2(190.9,64.75) 191.13,64.52 191.13,64.34 190.19,63.39 189.09,63.39 188.59,62.9 184.6,62.9 182.92,64.57 179.4,64.57 178.68,65.29 176.14,65.29 176.13,65.3 175.42,65.3 174.86,64.75 169.99,64.75 169.12,65.62 155.82,65.62 150.63,60.43 121.65,60.43 116.11,65.97 100.83,65.97 100.32,65.46 99.4,65.46 v2(99.19,65.68)
USB2_DN*<5>: length 165.6
  TOP w0.076: U1.AJ1 186.41,62.12 186.04,62.12 185.79,62.37 181.88,62.37 181.76,62.25 181.76,62.07 182.11,61.72 v2(182.23,61.72)
  TOP w0.109: FIL10.1 61.27,20.46 60.69,20.46 60.38,20.78 60.38,23.23 74.39,37.25 91.71,37.25 96.97,42.5 96.97,58.46 99.65,61.14 99.65,61.77 99.51,61.91 99.29,61.91 v2(99.01,61.63)
  LAY6 w0.076: 176.13,61.08 176.14,61.06 176.16,61.06 176.39,60.83 181.4,60.83 181.76,61.19 181.76,61.35 182.12,61.72 v2(182.23,61.72)
  LAY6 w0.087: v2(99.01,61.63) 99.01,61.7 99.36,62.05 113.18,62.05 117.93,57.31 127.11,57.31 127.58,56.84 135.33,56.84 135.6,57.11 137.36,57.11 137.64,56.84 148.39,56.84 149.19,56.04 151.48,56.04 157.15,61.71 158.48,61.71 158.87,61.32 161.29,61.32 161.77,61.79 171.15,61.79 171.32,61.63 173.3,61.63 173.72,62.06 175.15,62.06 176.13,61.08
USB2_DN*<7>: length 149.4
  TOP w0.076: v2(178.19,63.97) 178.41,63.74 178.41,63.3 178.83,62.89 186.1,62.89 186.17,62.81 186.17,62.62 186.26,62.53 186.41,62.53 186.48,62.59 186.48,62.81 186.55,62.89 186.81,62.89 186.88,62.82 186.88,62.7 U1.AH1
  LAY3 w0.087: v2(81.34,69.63) 81.09,69.87 81.09,95.49 78.81,97.77 77.47,97.77 v2(77.27,97.97)
  LAY6 w0.076: 176.13,63.87 176.27,64.01 176.27,64.03 176.3,64.06 176.3,64.07 176.83,64.6 178.23,64.6 178.42,64.41 178.42,64.2 v2(178.19,63.97)
  LAY6 w0.087: 176.13,63.87 175.8,63.55 169.22,63.55 167.99,64.77 156.72,64.77 150.35,58.4 145.98,58.4 145.17,59.22 121.3,59.22 116.17,64.34 90.9,64.34 84.91,70.33 81.37,70.33 81.1,70.06 81.1,69.87 v2(81.34,69.63)
  BOTTOM w0.124: U95.2 76.57,97.91 76.7,97.79 77.09,97.79 v2(77.27,97.97)
USB2_DP<1>: length 206.1
  TOP w0.076: U1.AB10 v2(191.54,65.81)
  TOP w0.109: v2(8.58,87.32) 8.79,87.53 8.79,88.44 FIL5.4
  LAY6 w0.076: 176.13,67.04 176.15,67.04 176.16,67.03 182.04,67.03 182.21,67.19 186.42,67.19 187.15,66.46 191.06,66.46 191.3,66.21 191.3,66.05 v2(191.54,65.81)
  LAY6 w0.087: v2(8.58,87.32) 8.58,87.99 8.98,88.39 20.71,88.39 22.29,89.97 27.85,89.97 29.71,88.11 33.64,88.11 34.29,88.75 37.36,88.75 40.14,85.98 40.14,80.59 46.98,73.74 71.27,73.74 72.99,72.02 87.52,72.02 91.71,67.83 116.98,67.83 122.72,62.09 149.6,62.09 155.58,68.07 163.04,68.07 163.42,67.69 169.44,67.69 170.32,66.81 171.14,66.81 171.85,67.52 172.67,67.52 173.16,67.04 176.13,67.04
USB2_DP<2>: length 174.1
  TOP w0.076: U1.AD7 v2(189.63,64.75)
  TOP w0.109: v2(35.49,88.06) 35.36,88.2 FIL15.4
  LAY6 w0.087: v2(189.63,64.75) 189.63,64.14 189.38,63.88 188.72,63.88 188.18,64.41 183.95,64.41 183.43,64.93 179.6,64.93 178.84,65.7 176.42,65.7 176.18,65.94 169.67,65.94 168.94,66.67 155.69,66.67 150.04,61.02 122.09,61.02 116.28,66.82 91.34,66.82 87.06,71.11 69.88,71.11 68.34,72.65 45.77,72.65 35.53,82.89 35.53,88.03 v2(35.49,88.06)
USB2_DP<3>: length 102.3
  TOP w0.076: U1.AJ3 187.89,62.07 187.89,62.26 187.77,62.38 187.61,62.38 187.5,62.26 187.5,61.9 187.38,61.78 187.37,61.77 187.22,61.73 187.11,61.73 186.99,61.78 186.97,61.8 186.76,61.8 186.57,61.72 186.57,61.72 186.18,61.72 185.93,61.97 183.13,61.97 182.37,61.21 177.63,61.21 176.29,59.87 176.26,59.87 176.24,59.86
  TOP w0.102: 176.13,59.74 176.24,59.86
  TOP w0.109: v2(126.69,13.82) 126.51,14 125.29,14 125.15,13.86 CN26.3 ; v2(170.7,37.11) 170.88,37.28 170.88,50.84 174.61,54.57 174.61,58.24 175.98,59.6 175.99,59.6 176.13,59.74
  LAY6 w0.087: v2(170.7,37.11) 170.9,36.91 170.9,30.1 161.77,20.96 161.77,19.83 157.36,15.42 126.27,15.42 125.69,14.84 125.69,14.05 125.93,13.82 v2(126.69,13.82)
USB2_DP<4>: length 187.2
  TOP w0.076: U1.AD10 191.86,65.07 v2(191.54,64.75)
  TOP w0.109: FIL9.2 45.69,20.63 45.32,20.63 45.17,20.79 45.17,22.89 60.51,38.24 91.34,38.24 96.04,42.93 96.04,59.01 97.06,60.03 97.06,64.22 98.3,65.46 98.8,65.46 v2(99.19,65.07)
  LAY6 w0.087: v2(99.19,65.07) 99.39,65.28 100.4,65.28 100.91,65.79 116.03,65.79 121.58,60.24 150.71,60.24 155.9,65.43 169.05,65.43 169.92,64.56 174.94,64.56 175.49,65.12 178.6,65.12 179.32,64.4 182.85,64.4 184.52,62.72 188.66,62.72 189.16,63.22 190.26,63.22 191.31,64.26 191.31,64.51 v2(191.54,64.75)
USB2_DP<5>: length 165.6
  TOP w0.076: U1.AJ2 186.94,62.01 186.66,62.29 186.11,62.29 185.86,62.54 181.81,62.54 181.59,62.32 v2(181.59,61.72)
  TOP w0.109: v2(99.01,62.23) 99.11,62.12 99.6,62.12 99.87,61.86 99.87,61.04 97.19,58.37 97.19,42.41 91.81,37.03 74.48,37.03 60.6,23.14 60.6,20.87 60.78,20.68 61.27,20.68 FIL10.4
  LAY6 w0.076: v2(181.59,61.72) 181.59,61.26 181.33,60.99 176.46,60.99 176.27,61.18 176.27,61.19 176.26,61.21
  LAY6 w0.087: 176.26,61.21 175.23,62.24 173.65,62.24 173.22,61.81 171.39,61.81 171.23,61.98 161.69,61.98 161.21,61.5 158.95,61.5 158.55,61.9 157.08,61.9 151.4,56.22 149.27,56.22 148.46,57.02 137.71,57.02 137.44,57.3 135.53,57.3 135.25,57.02 127.65,57.02 127.19,57.49 118,57.49 113.26,62.23 v2(99.01,62.23)
USB2_DP<7>: length 149.4
  TOP w0.076: U1.AH2 187.32,62.67 186.94,63.05 178.9,63.05 178.58,63.37 178.58,63.73 v2(178.82,63.97)
  LAY3 w0.087: v2(80.73,69.63) 80.91,69.81 80.91,95.41 78.74,97.59 77.47,97.59 v2(77.27,97.39)
  LAY6 w0.076: v2(178.82,63.97) 178.59,64.2 178.59,64.48 178.3,64.77 176.76,64.77 176.13,64.13
  LAY6 w0.087: 176.13,64.13 175.73,63.73 169.29,63.73 168.06,64.96 156.64,64.96 150.27,58.59 146.06,58.59 145.24,59.4 121.37,59.4 116.25,64.52 90.98,64.52 84.99,70.51 81.29,70.51 80.92,70.14 80.92,69.82 v2(80.73,69.63)
  BOTTOM w0.124: v2(77.27,97.39) 77.12,97.54 76.7,97.54 76.57,97.41 U95.3
USB2_OC*<0>: length 193
  TOP w0.076: U1.A9 191.03,77.6 191.03,78.1 v2(190.56,78.57) 189.8,79.33
  TOP w0.102: 189.8,79.33 189.62,79.51 R63.2
  LAY6 w0.102: v2(25.74,92.18) 29.33,92.18 29.93,91.58 38.66,91.58 45.22,85.02 84.09,85.02 95.52,73.59 110.71,73.59 111.42,74.3 121.19,74.3 124.45,71.04 138.04,71.04 139.2,72.2 149.78,72.2 152.05,74.47 164.37,74.47 165.54,75.64 v2(165.82,75.64)
  BOTTOM w0.102: v2(190.56,78.57) 190.4,78.74 182.01,78.74 179.66,81.09 175.65,81.09 173.33,78.77 168.8,78.77 165.82,75.79 v2(165.82,75.64)
  BOTTOM w0.203: U12.3 21.9,89.4 R339.1 22.8,89.9 R341.2 23.77,89.71 C410.1 24.8,89.71 25.74,90.65 v2(25.74,92.18)
USB2_OC*<1>: length 7
  TOP w0.076: R64.2 190.4,79.29 191.21,78.48 191.21,77.84 191.44,77.61 191.44,77.34 191.39,77.23 191.39,77.08 191.44,76.89 191.44,76.71 191.36,76.46 U1.C9
USB2_OC*<2>: length 7.5
  TOP w0.076: U1.D9 191.39,75.83 191.47,76.09 191.47,76.21 191.61,76.69 191.61,76.94 191.57,77.03 191.57,77.22 191.61,77.32 191.61,77.68 191.39,77.9 191.39,79.25 191.18,79.46 R65.2
USB2_OC*<3>: length 6.8
  TOP w0.076: U1.B9 190.85,77.13 190.85,77.65 189.49,79.02
  TOP w0.102: 189.49,79.02 188.85,79.66 R68.2
USB3_P1_PWREN: length 182.5
  TOP w0.076: U1.AD2 186.95,64.66 186.78,64.82 arc(186.67,64.91) 186.53,64.94 183.6,64.94 182.26,63.6 181.76,63.6 v2(181.39,63.97)
  LAY6 w0.076: 176.2,62.76 180.18,62.76 v2(181.39,63.97)
  LAY6 w0.102: 176.2,62.76 168.61,62.76 167.45,63.91 157.24,63.91 150.83,57.5 145.24,57.5 144.63,58.11 135.22,58.11 134.94,57.83 133.81,57.83 133.11,58.53 121.19,58.53 115.93,63.79 85.39,63.79 79.25,69.92 69.35,69.92 67.85,71.42 46.26,71.42 31.46,86.22 31.46,86.8 30.87,87.4 29.32,87.4 27.55,89.16 v2(24.78,89.16)
  BOTTOM w0.203: U12.4 24.78,88.48 R342.2 24.79,89.15 v2(24.78,89.16)
USB3_PWRON: length 112.4
  TOP w0.203: v2(45.83,30.88) 45.83,30.81 40.09,25.07 R563.2 40.09,21.5 40.28,21.31 U39.4 ; v2(56.13,30.08) 57.09,29.12 57.09,12.87 57.78,12.18 R558.2 U40.4
  LAY3 w0.102: v2(45.83,30.88) 45.9,30.88 51.25,36.23 51.25,53.04 51.8,53.59 51.8,58.54 51.25,59.09 51.25,68.64 50.03,69.86 50.03,81.1 51.85,82.91 51.85,91.7 v2(51.51,92.05)
  LAY6 w0.102: v2(45.83,30.88) 55.28,30.88 56.1,30.06 v2(56.13,30.08)
  BOTTOM w0.102: U38.4 50.21,90.51 R561.2 v2(51.51,92.05)
USB3_RX_DN*<1>: length 203.1
  TOP w0.076: U1.H8 191.24,72.78 v2(191.47,73.05)
  TOP w0.124: v2(5.48,88.02) 5.74,88.28 5.74,88.66 FIL6.4
  LAY6 w0.087: v2(191.47,73.05) 191.14,73.38 190.92,73.61 190.92,73.9 190.71,74.11 188.78,74.11 188.39,73.72 186.12,73.72 185.18,74.65 181.93,74.65 181.08,73.81 181.07,73.81 180.62,73.35 178.96,73.35 178.63,73.02 178.45,73.02 178.44,73.01 178.2,73.01 178.19,73.02 173.95,73.02 173.41,73.57 152.41,73.57 150.08,71.24 140.71,71.24 139.62,70.15 123.85,70.15 120.64,73.36 112.57,73.36 111.9,72.69 94.93,72.69 83.81,83.8 45.25,83.8 38.28,90.78 29.22,90.78 28.9,91.09 22.48,91.09 20.29,88.9 8.75,88.9 6.84,86.99 5.87,86.99 5.5,87.35 5.5,87.99 v2(5.48,88.02)
USB3_RX_DN*<2>: length 177.7
  TOP w0.076: U1.J6 189.93,72.13 v2(189.65,72.41)
  TOP w0.109: v2(31,88.95) 30.82,88.95 30.45,88.58 30.45,88.06 30.86,87.64 32.82,87.64 32.95,87.76 32.95,88.07 32.81,88.21 32.57,88.21 32.36,88.41 FIL16.4
  LAY6 w0.076: v2(189.65,72.41) 189.41,72.65 189.01,72.65 188.6,73.06 185.97,73.06 185.47,73.55 183.76,73.55 182.94,72.73 179.08,72.73 178.72,72.37 177.83,72.37 177.82,72.36 177.8,72.36
  LAY6 w0.087: 177.8,72.36 173.57,72.36 173.03,72.91 152.79,72.91 150.47,70.59 141.33,70.59 140.15,69.41 122.94,69.41 120.32,72.03 115.21,72.03 114.8,71.62 112.35,71.62 111.94,72.03 94.43,72.03 83.53,82.94 44.75,82.94 38.45,89.24 33.27,89.24 32.67,89.84 30.64,89.84 30.41,89.61 30.41,89.3 30.76,88.95 v2(31,88.95)
USB3_RX_DP<1>: length 203
  TOP w0.076: v2(191.47,73.68) 191.24,73.43 U1.G8
  TOP w0.124: v2(6.25,88.02) 5.99,88.28 5.99,88.66 FIL6.1
  LAY6 w0.087: v2(6.25,88.02) 6,88.02 5.69,87.71 5.69,87.43 5.94,87.17 6.76,87.17 8.67,89.09 20.22,89.09 22.4,91.27 28.98,91.27 29.29,90.96 38.35,90.96 45.33,83.99 83.89,83.99 95,72.87 111.82,72.87 112.49,73.54 120.71,73.54 123.92,70.33 139.54,70.33 140.64,71.43 150.01,71.43 152.33,73.75 173.48,73.75 174.03,73.2 178.27,73.2 178.28,73.2 178.56,73.2 178.89,73.53 180.55,73.53 181.86,74.84 185.25,74.84 186.19,73.89 188.32,73.89 188.71,74.29 190.78,74.29 191.09,73.97 191.09,73.68 191.21,73.56 191.35,73.56 v2(191.47,73.68)
USB3_RX_DP<2>: length 177.7
  TOP w0.076: U1.H6 189.91,72.78 v2(189.65,73.05)
  TOP w0.109: v2(30.23,88.95) 30.23,87.97 30.77,87.42 32.92,87.42 33.17,87.67 33.17,88.56 FIL16.1
  LAY6 w0.076: 177.8,72.54 177.82,72.54 177.83,72.53 178.65,72.53 179.01,72.89 182.87,72.89 183.69,73.72 185.54,73.72 186.03,73.22 188.67,73.22 189.08,72.81 189.41,72.81 v2(189.65,73.05)
  LAY6 w0.087: v2(30.23,88.95) 30.23,89.68 30.57,90.02 32.75,90.02 33.34,89.42 38.52,89.42 44.82,83.12 83.6,83.12 94.51,72.22 112.02,72.22 112.43,71.81 114.72,71.81 115.13,72.22 120.39,72.22 123.02,69.59 140.07,69.59 141.25,70.77 150.4,70.77 152.72,73.09 173.1,73.09 173.65,72.54 177.8,72.54
USB3_TX_DN*<1>: length 195.2
  TOP w0.076: v2(193.73,84.21) 193.66,84.21 193.55,84.1 193.55,83.92 193.65,83.82 194.06,83.82 194.17,83.71 194.17,80.18 193.62,79.62 193.62,78.08 193.92,77.77 193.92,77.34 193.86,77.23 193.86,77.08 193.92,76.89 193.92,76.71 193.84,76.46 U1.C13
  TOP w0.109: C411.2 19.81,91.37
  TOP w0.124: v2(20.62,91.15) 20.4,91.37 19.81,91.37
  LAY6 w0.076: v2(193.73,84.21) 193.86,84.21 194,84.35 194,84.51 193.9,84.6 189.97,84.6 189.97,84.6 189.92,84.6 189.91,84.59 189.9,84.59
  LAY6 w0.087: v2(20.62,91.15) 20.62,91.39 20.87,91.63 21.83,91.63 22.43,92.23 24.87,92.23 25.93,93.28 38.94,93.28 45.03,87.19 85.32,87.19 88.77,83.74 108.34,83.74 109.66,82.43 136.2,82.43 137.01,81.61 140,81.61 140.78,80.83 143.25,80.83 144.64,82.22 152.41,82.22 156,85.82 170.64,85.82 173.16,88.34 177.95,88.34 179.77,86.52 185.9,86.52 187.83,84.59 189.9,84.59
USB3_TX_DN*<2>: length 171.2
  TOP w0.076: U1.B13 193.59,76.87 193.19,76.87 192.94,77.11 192.94,84.66 193.3,85.02 193.3,85.39 v2(193.08,85.61)
  TOP w0.109: C2762.2 43.96,89.68 44.72,89.68 45.05,90.02 v2(45.05,91.34)
  LAY6 w0.076: 191.13,85.78 191.71,85.2 193.29,85.2 193.38,85.28 193.38,85.43 193.2,85.61 v2(193.08,85.61)
  LAY6 w0.087: 191.13,85.78 190.25,86.66 187.23,86.66 186.45,87.44 180.09,87.44 178.14,89.38 167.55,89.38 167,88.84 161.99,88.84 160.41,87.26 155.76,87.26 151.94,83.43 142.88,83.43 142,82.56 137.37,82.56 136.43,83.5 129.49,83.5 129.06,83.93 109.7,83.93 108.82,84.81 89.2,84.81 85.79,88.21 46.65,88.21 44.46,90.4 44.46,90.95 44.6,91.08 44.92,91.08 45.05,91.22 v2(45.05,91.34)
USB3_TX_DP<1>: length 195.2
  TOP w0.076: U1.D13 193.87,75.83 193.95,76.09 193.95,76.21 194.09,76.69 194.09,76.94 194.05,77.03 194.05,77.22 194.09,77.32 194.09,77.84 193.78,78.14 193.78,79.56 194.34,80.11 v2(194.34,84.21)
  TOP w0.124: C412.2 19.9,91.62 20.31,91.62 v2(20.62,91.93)
  LAY6 w0.076: v2(194.34,84.21) 194.16,84.38 194.16,84.58 193.97,84.77 189.9,84.77
  LAY6 w0.087: v2(20.62,91.93) 20.73,91.82 21.76,91.82 22.35,92.41 24.8,92.41 25.85,93.47 39.01,93.47 45.11,87.37 85.39,87.37 88.84,83.92 108.42,83.92 109.73,82.61 136.28,82.61 137.09,81.8 140.07,81.8 140.86,81.01 143.17,81.01 144.56,82.41 152.33,82.41 155.93,86.01 170.57,86.01 173.08,88.52 178.02,88.52 179.84,86.7 185.97,86.7 187.9,84.77 189.9,84.77
USB3_TX_DP<2>: length 171.2
  TOP w0.076: U1.A13 193.66,77.25 193.44,77.03 193.26,77.03 193.11,77.18 193.11,84.6 193.46,84.95 193.46,85.39 v2(193.68,85.61)
  TOP w0.109: v2(44.28,91.34) 44.44,91.34 44.84,90.94 44.84,90.11 44.63,89.9 44.08,89.9 C2763.2
  LAY6 w0.076: v2(193.68,85.61) 193.54,85.46 193.54,85.21 193.36,85.03 191.64,85.03 191.08,85.59 191.08,85.59
  LAY6 w0.087: v2(44.28,91.34) 44.28,90.32 46.58,88.03 85.72,88.03 89.12,84.62 108.74,84.62 109.62,83.75 128.99,83.75 129.42,83.32 136.35,83.32 137.29,82.38 142.08,82.38 142.96,83.25 152.01,83.25 155.83,87.07 160.48,87.07 162.06,88.65 167.08,88.65 167.62,89.2 178.07,89.2 180.01,87.25 186.38,87.25 187.15,86.48 190.17,86.48 190.41,86.24 190.42,86.24 191.07,85.59 191.08,85.59
USB_OC1#: length 4
  BOTTOM w0.203: U38.3 47.7,91.91 C710.1 ; R560.2 48.71,91.93 C710.1 ; C710.1 47.67,91.94 R559.1
USB_OC2#: length 38
  TOP w0.203: U39.3 43.05,22.05 C713.1 43.47,23.28 R562.2 43.28,23.53 42.07,24.74 R569.1 42.07,25.83 46.41,30.17 v2(46.45,30.17) ; U40.3 59.27,15.94 C661.1 58.13,17.28 R570.1 R557.2 58.29,28.91 v2(57.74,29.46)
  LAY6 w0.102: v2(57.74,29.46) 47.16,29.46 v2(46.45,30.17)
USB_WAKEOUT_INTRUDET*: length 24
  TOP w0.076: U1.AT15 v2(195.13,58.24)
  LAY6 w0.076: 184.56,54.25 190.72,54.25 193.86,57.39 193.86,59.12 194.1,59.36 194.53,59.36 194.7,59.19 194.7,58.68 v2(195.13,58.24)
  LAY6 w0.102: v2(176.85,51.22) 177.33,51.71 182.02,51.71 184.56,54.25
VCLK: length 8.5
  BOTTOM w0.203: U71.19 17.63,70.94 17.93,70.65 20.59,70.65 C779.1 24.46,67.65 C770.1
VFB1: length 4.5
  BOTTOM w0.203: U71.2 16.36,69.58 16.55,69.39 17.54,69.39 R784.1 R782.2
VFB2: length 3
  BOTTOM w0.203: 15.89,68.74 15.56,69.07 U71.4
  BOTTOM w0.305: 15.89,68.74 R785.1
  BOTTOM w0.508: R785.1 R776.1
VREFA: length 3.7
  TOP w0.305: U2529.12 127.22,86.04 C992.1 128.78,85.73 R3112.2
VREG3: length 19.1
  LAY6 w0.203: v2(20,70.19) 18.05,68.25 v2(16.79,68.25)
  BOTTOM w0.203: v2(20,70.19) 19.87,70.07 R780.2 ; v2(16.79,68.25) 16.79,65.81 16.32,65.34 12.9,65.34 12.49,65.74 12.49,69.53 R775.1 ; U71.3 15.96,69.41
  BOTTOM w0.305: 17.04,68.94 16.43,68.94 15.96,69.41
  BOTTOM w0.406: 17.04,68.94 17.48,68.5 C774.1 16.84,68.24 16.83,68.25 v2(16.79,68.25)
VREG5: length 2.8
  BOTTOM w0.203: 15.96,73.57 U71.13
  BOTTOM w0.406: C773.2 16.76,74.96 15.96,74.17 15.96,73.57
WIFI_CLK_REQ*: length 127.5
  TOP w0.076: U1.AT8 190.95,58.59 v2(190.58,58.23)
  TOP w0.109: v2(119.53,54.62) 116.77,51.86 116.77,44.09 117.51,43.35 117.51,30.31 120.44,27.38 121.94,27.38 122.96,26.36 CN26.53
  LAY6 w0.076: v2(190.58,58.23) 190.06,58.23 189.88,58.05 184.12,58.05 180.14,54.07 176.69,54.07 176.13,54.63
  LAY6 w0.087: v2(119.53,54.62) 120.08,54.62 120.53,54.17 123.86,54.17 124.33,54.64 146.66,54.64 147.03,54.28 155.19,54.28 156.19,55.28 158.37,55.28 158.51,55.14 167.76,55.14 168.69,56.07 170.86,56.07 171.66,55.27 175.49,55.27 176.13,54.63
  BOTTOM w0.102: 176.13,53.65 179.54,53.65 181.42,55.53 181.43,55.53 184.13,58.23 v2(190.58,58.23)
  BOTTOM w0.109: R2.2 176.13,53.65
WIFI_PCIE_CLK_DN: length 146.9
  TOP w0.076: U1.D41 210.44,76.06 210.15,76.36 210.15,76.81 210.37,77.03 210.37,77.57 210.81,78.01 210.81,78.72 210.71,78.82 210.41,78.82 v2(210.35,78.76)
  TOP w0.109: CN26.49 125.2,25.36 125.34,25.22 126.09,25.22 127.21,26.34 127.21,29.76 126.85,30.12 126.85,35.52 127.51,36.18 127.51,49.03 v2(127.32,49.22)
  LAY6 w0.076: v2(210.35,78.76) 210.31,78.81 207.91,78.81 207.38,79.35 206.17,79.35 204.04,81.48 202.91,81.48 202.74,81.3 202.74,81.02 201.7,79.98 195.9,79.98 195.16,79.24 189.95,79.24 189.95,79.23 189.9,79.23 189.89,79.22 189.88,79.22
  LAY6 w0.087: v2(128.59,76.32) 128.78,76.13 128.78,75.64 129.09,75.33 134.57,75.33 134.88,75.02 144.16,75.02 144.94,75.8 149.31,75.8 150.96,77.45 158.58,77.45 160.58,79.46 164.13,79.46 164.8,80.13 167.52,80.13 167.97,79.68 171.86,79.68 172.62,78.93 175.04,78.93 176.42,80.3 180.6,80.3 181.69,79.22 189.88,79.22
  BOTTOM w0.109: v2(128.59,76.32) 128.75,76.16 128.75,75.53 127.51,74.3 127.51,49.41 v2(127.32,49.22)
